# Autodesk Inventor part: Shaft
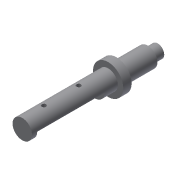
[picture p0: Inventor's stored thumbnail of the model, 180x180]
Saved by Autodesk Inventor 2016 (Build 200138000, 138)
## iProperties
Created: 2009-04
Part Number: Shaft
Document SubType Name: Modeling
Designer: Sham
Density: 1 g/cm^3
Material: Generic
Appearance: Default
Author: Sham
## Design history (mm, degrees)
sketch "Sketch1"
  geometry: C1 r 18.75 at (511.175, 103.188)
  constraints: 1 centre point
  dimensions: "d0" = 37.5 diameter of C1
extrude "Extrusion1" new body sketch "Sketch1" distance "d1" = 28.9; taper "d2" = 0 deg
sketch "Sketch2"
  geometry: C1 r 28 at (0, 0)
  constraints: 1 centre point
  dimensions: "d3" = 56 diameter of C1
extrude "Extrusion2" join sketch "Sketch2" distance "d4" = 89.8; taper "d5" = 0 deg
sketch "Sketch3"
  geometry: C1 r 43.6 at (0, 0)
  constraints: 1 centre point
  dimensions: "d6" = 87.2 diameter of C1
extrude "Extrusion3" join sketch "Sketch3" distance "d7" = 24; taper "d8" = 0 deg
sketch "Sketch4"
  geometry: C1 r 43.6 at (0, 0) reference; C2 r 28 at (0, 0)
  constraints: 1 centre point, 1 coincident
  dimensions: "d9" = 56 diameter of C2
extrude "Extrusion4" join sketch "Sketch4" distance "d10" = 247.1; taper "d11" = 0 deg
workplane "Work Plane1"
sketch "Sketch5"
  geometry: L1 (28, 0)-(-28, 0); C1 r 43.6 at (0, 0) reference; A1 r 28 centre (0, 0) between (-28, 0) and (28, 0)
  constraints: 2 end point, 2 point on circle, 1 centre point, 1 concentric, 1 horizontal
  dimensions: "d13" = 56 diameter of A1
extrude "Extrusion5" cut sketch "Sketch5" distance "d14" = 193.8; taper "d15" = 0 deg
hole "Hole1" diameter "d18" = 12.5; stored, may be unused: countersink angle "d22" = 90 deg, drill point angle "d24" = 118 deg; dims "d16" = 28, "d17" = 46.9, "d19" = 6, "d20" = 4, "d21" = 2, "d23" = 8
pattern_linear "Rectangular Pattern1" dims "d27" = 100
body "Solid1"
other parameters: "d12" = -15.1
